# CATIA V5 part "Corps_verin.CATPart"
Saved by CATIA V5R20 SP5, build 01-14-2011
Part number: Corps_verin
Publications: "Droite.1", "Droite.2"
Bounding box of the stored display mesh (mm): x 0 to 200, y 68.933 to 233.933, z 128.204 to 128.204
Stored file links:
  J:\Thinkmotion\Projet IAO\A envoyer\Corps_verin.CATPart
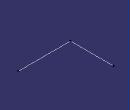
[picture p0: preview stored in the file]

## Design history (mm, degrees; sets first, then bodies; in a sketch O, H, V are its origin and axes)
Set1
  Line1: type PtPt, FirstPoint Point1, SecondPoint Point2
  Point1 "F": stored without definition
  Point2 "V": stored without definition
  Line2: type Normal, RefPoint Point3, RefSkin yz-plane, Start 0, End 200
  Point3 "F": stored without definition
Body1 (main body)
